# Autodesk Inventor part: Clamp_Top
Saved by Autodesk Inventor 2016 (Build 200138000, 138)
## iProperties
Created: 2015-11
Part Number: Clamp_Top
Material: Generic
Document SubType Name: Modeling
Designer: John
Density: 1 g/cm^3
Appearance: Default
Author: John
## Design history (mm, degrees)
feature "Base1"
body "Solid1"
